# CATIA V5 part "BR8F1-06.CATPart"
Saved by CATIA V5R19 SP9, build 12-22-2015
Part number: BR8F1-06
Definition: design
Nomenclature: BR8F1-06
Source: Unknown
Bounding box of the stored display mesh (mm): x -3.9 to 11.15, y 0 to 18.1, z 0 to 30.48
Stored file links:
  Z:\charly_robot\BR8F1-06.CATPart
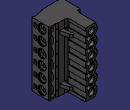
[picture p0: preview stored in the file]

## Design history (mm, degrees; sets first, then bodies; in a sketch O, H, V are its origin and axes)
AxisSystem1: origin (0, 0, 0), X (1, 0, 0), Y (0, 1, 0), Z (0, 0, 1)
Body1 "MANIFOLD_SOLID_BREP #102016" (main body)
  Solid1: solid without history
